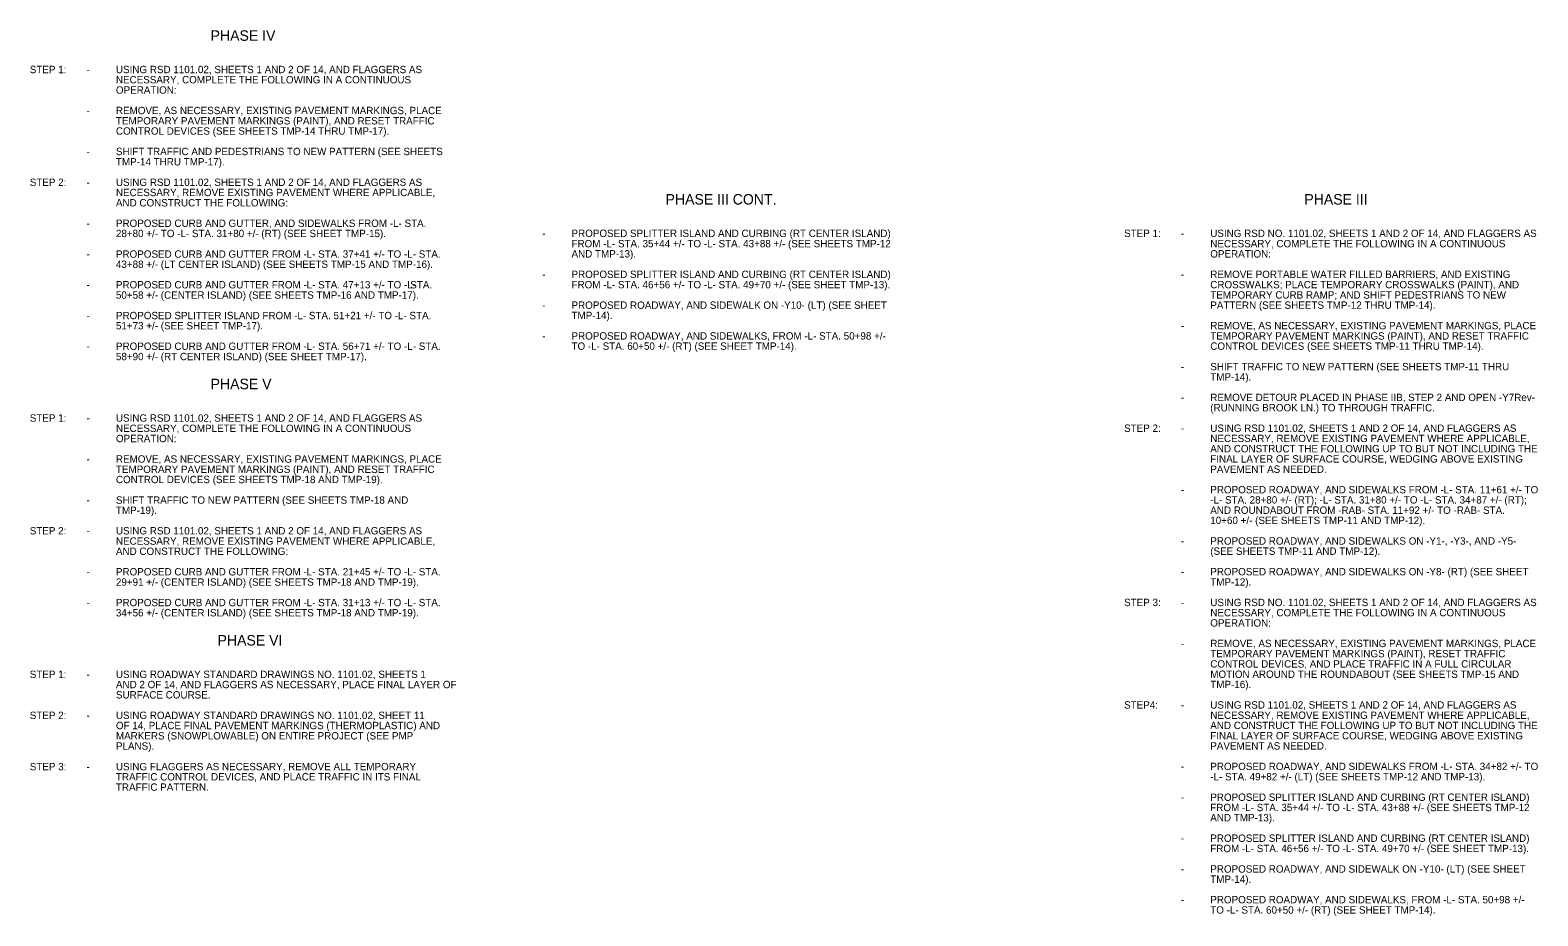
# Model space of a CAD drawing. Extents: x 764226 to 769781, y 650021 to 652521.
# Drawn here: x 768347 to 769781, y 651597 to 652440 of the extents above; entities that cross this region are included whole.
import ezdxf

# ---------------------------------------------------------------- set-up
doc = ezdxf.new("R2010")
doc.units = 0
doc.layers.add('Default', color=7, linetype='Continuous')

msp = doc.modelspace()

# ---------------------------------------------------------------- texts
at = {"layer": 'Default'}
for s, height, p in [('PHASE IV', 10, (768518.4, 652430)), ('STEP 1:', 7, (768346.3, 652399.2)), ('-', 7, (768400.3, 652399.2)), ('USING RSD 1101.02, SHEETS 1 AND 2 OF 14, AND FLAGGERS AS ', 7, (768428.3, 652399.2)), ('OPERATION:', 7, (768428.3, 652379.7)), ('NECESSARY, COMPLETE THE FOLLOWING IN A CONTINUOUS ', 7, (768428.3, 652389.5)), ('-', 7, (768400.3, 652360.2)), ('TEMPORARY PAVEMENT MARKINGS (PAINT), AND RESET TRAFFIC ', 7, (768428.3, 652350.4)), ('REMOVE, AS NECESSARY, EXISTING PAVEMENT MARKINGS, PLACE ', 7, (768428.3, 652360.2)), ('CONTROL DEVICES (SEE SHEETS TMP-14 THRU TMP-17).', 7, (768428.3, 652340.7)), ('-', 7, (768400.3, 652321.2)), ('TMP-14 THRU TMP-17).', 7, (768428.3, 652311.4)), ('SHIFT TRAFFIC AND PEDESTRIANS TO NEW PATTERN (SEE SHEETS ', 7, (768428.3, 652321.2)), ('STEP 2:', 7, (768346.3, 652291.9)), ('-', 7, (768400.3, 652291.9)), ('USING RSD 1101.02, SHEETS 1 AND 2 OF 14, AND FLAGGERS AS ', 7, (768428.3, 652291.9)), ('NECESSARY, REMOVE EXISTING PAVEMENT WHERE APPLICABLE, ', 7, (768428.3, 652282.2)), ('AND CONSTRUCT THE FOLLOWING:', 7, (768428.3, 652272.4)), ('PHASE III CONT.', 10, (768951.3, 652274.2)), ('PHASE III', 10, (769559.1, 652274.2)), ('PROPOSED CURB AND GUTTER, AND SIDEWALKS FROM -L- STA. ', 7, (768428.3, 652252.9)), ('-', 7, (768400.3, 652252.9)), ('28+80 +/- TO -L- STA. 31+80 +/- (RT) (SEE SHEET TMP-15). ', 7, (768428.3, 652243.2)), ('-', 7, (768833.8, 652243.3)), ('PROPOSED SPLITTER ISLAND AND CURBING (RT CENTER ISLAND) ', 7, (768861.8, 652243.3)), ('STEP 1:', 7, (769387.6, 652243.3)), ('-', 7, (769441.6, 652243.3)), ('USING RSD NO. 1101.02, SHEETS 1 AND 2 OF 14, AND FLAGGERS AS ', 7, (769469.6, 652243.3)), ('PROPOSED CURB AND GUTTER FROM -L- STA. 37+41 +/- TO -L- STA. ', 7, (768428.3, 652223.6)), ('AND TMP-13).', 7, (768861.8, 652223.8)), ('FROM -L- STA. 35+44 +/- TO -L- STA. 43+88 +/- (SEE SHEETS TMP-12 ', 7, (768861.8, 652233.5)), ('OPERATION:', 7, (769469.6, 652223.8)), ('NECESSARY, COMPLETE THE FOLLOWING IN A CONTINUOUS ', 7, (769469.6, 652233.5)), ('-', 7, (768400.3, 652223.6)), ('43+88 +/- (LT CENTER ISLAND) (SEE SHEETS TMP-15 AND TMP-16).', 7, (768428.3, 652213.9)), ('PROPOSED CURB AND GUTTER FROM -L- STA. 47+13 +/- TO -L-', 7, (768428.3, 652194.4)), ('STA. ', 7, (768708.4, 652194.4)), ('-', 7, (768833.8, 652204.3)), ('PROPOSED SPLITTER ISLAND AND CURBING (RT CENTER ISLAND) ', 7, (768861.8, 652204.3)), ('FROM -L- STA. 46+56 +/- TO -L- STA. 49+70 +/- (SEE SHEET TMP-13).', 7, (768861.8, 652194.5)), ('-', 7, (769441.6, 652204.3)), ('CROSSWALKS; PLACE TEMPORARY CROSSWALKS (PAINT), AND ', 7, (769469.6, 652194.5)), ('REMOVE PORTABLE WATER FILLED BARRIERS, AND EXISTING ', 7, (769469.6, 652204.3)), ('-', 7, (768400.3, 652194.4)), ('50+58 +/- (CENTER ISLAND) (SEE SHEETS TMP-16 AND TMP-17).', 7, (768428.3, 652184.6)), ('TEMPORARY CURB RAMP; AND SHIFT PEDESTRIANS TO NEW ', 7, (769469.6, 652184.7)), ('PROPOSED SPLITTER ISLAND FROM -L- STA. 51+21 +/- TO -L- STA. ', 7, (768428.3, 652165.1)), ('-', 7, (768833.8, 652175)), ('TMP-14).', 7, (768861.8, 652165.2)), ('PROPOSED ROADWAY, AND SIDEWALK ON -Y10- (LT) (SEE SHEET ', 7, (768861.8, 652175)), ('PATTERN (SEE SHEETS TMP-12 THRU TMP-14).', 7, (769469.6, 652175)), ('-', 7, (768400.3, 652165.1)), ('51+73 +/- (SEE SHEET TMP-17).', 7, (768428.3, 652155.4)), ('-', 7, (769441.6, 652155.5)), ('REMOVE, AS NECESSARY, EXISTING PAVEMENT MARKINGS, PLACE ', 7, (769469.6, 652155.5)), ('PROPOSED CURB AND GUTTER FROM -L- STA. 56+71 +/- TO -L- STA. ', 7, (768428.3, 652135.9)), ('-', 7, (768833.8, 652145.7)), ('TO -L- STA. 60+50 +/- (RT) (SEE SHEET TMP-14).', 7, (768861.8, 652136)), ('PROPOSED ROADWAY, AND SIDEWALKS, FROM -L- STA. 50+98 +/- ', 7, (768861.8, 652145.7)), ('TEMPORARY PAVEMENT MARKINGS (PAINT), AND RESET TRAFFIC ', 7, (769469.6, 652145.7)), ('CONTROL DEVICES (SEE SHEETS TMP-11 THRU TMP-14).', 7, (769469.6, 652136)), ('-', 7, (768400.3, 652135.9)), ('58+90 +/- (RT CENTER ISLAND) (SEE SHEET TMP-17).', 7, (768428.3, 652126.1)), ('-', 7, (769441.6, 652116.5)), ('TMP-14).', 7, (769469.6, 652106.7)), ('SHIFT TRAFFIC TO NEW PATTERN (SEE SHEETS TMP-11 THRU ', 7, (769469.6, 652116.5)), ('PHASE V', 10, (768518.4, 652098.5)), ('-', 7, (769441.6, 652087.2)), ('REMOVE DETOUR PLACED IN PHASE IIB, STEP 2 AND OPEN -Y7Rev- ', 7, (769469.6, 652087.2)), ('STEP 1:', 7, (768346.3, 652067.6)), ('-', 7, (768400.3, 652067.6)), ('USING RSD 1101.02, SHEETS 1 AND 2 OF 14, AND FLAGGERS AS ', 7, (768428.3, 652067.6)), ('(RUNNING BROOK LN.) TO THROUGH TRAFFIC.', 7, (769469.6, 652077.4)), ('NECESSARY, COMPLETE THE FOLLOWING IN A CONTINUOUS ', 7, (768428.3, 652057.8)), ('STEP 2:', 7, (769387.6, 652057.9)), ('-', 7, (769441.6, 652057.9)), ('USING RSD 1101.02, SHEETS 1 AND 2 OF 14, AND FLAGGERS AS ', 7, (769469.6, 652057.9)), ('OPERATION:', 7, (768428.3, 652048.1)), ('AND CONSTRUCT THE FOLLOWING UP TO BUT NOT INCLUDING THE ', 7, (769469.6, 652038.4)), ('NECESSARY, REMOVE EXISTING PAVEMENT WHERE APPLICABLE, ', 7, (769469.6, 652048.2)), ('-', 7, (768400.3, 652028.6)), ('REMOVE, AS NECESSARY, EXISTING PAVEMENT MARKINGS, PLACE ', 7, (768428.3, 652028.6)), ('FINAL LAYER OF SURFACE COURSE, WEDGING ABOVE EXISTING ', 7, (769469.6, 652028.7)), ('TEMPORARY PAVEMENT MARKINGS (PAINT), AND RESET TRAFFIC ', 7, (768428.3, 652018.8)), ('CONTROL DEVICES (SEE SHEETS TMP-18 AND TMP-19).', 7, (768428.3, 652009.1)), ('PAVEMENT AS NEEDED.', 7, (769469.6, 652018.9)), ('-', 7, (769441.6, 651999.4)), ('PROPOSED ROADWAY, AND SIDEWALKS FROM -L- STA. 11+61 +/- TO ', 7, (769469.6, 651999.4)), ('-', 7, (768400.3, 651989.5)), ('TMP-19).', 7, (768428.3, 651979.8)), ('SHIFT TRAFFIC TO NEW PATTERN (SEE SHEETS TMP-18 AND ', 7, (768428.3, 651989.5)), ('AND ROUNDABOUT FROM -RAB- STA. 11+92 +/- TO -RAB- STA. ', 7, (769469.6, 651979.9)), ('-L- STA. 28+80 +/- (RT); -L- STA. 31+80 +/- TO -L- STA. 34+87 +/- (RT); ', 7, (769469.6, 651989.7)), ('10+60 +/- (SEE SHEETS TMP-11 AND TMP-12). ', 7, (769469.6, 651970.2)), ('STEP 2:', 7, (768346.3, 651960.3)), ('-', 7, (768400.3, 651960.3)), ('USING RSD 1101.02, SHEETS 1 AND 2 OF 14, AND FLAGGERS AS ', 7, (768428.3, 651960.3)), ('NECESSARY, REMOVE EXISTING PAVEMENT WHERE APPLICABLE, ', 7, (768428.3, 651950.5)), ('PROPOSED ROADWAY, AND SIDEWALKS ON -Y1-, -Y3-, AND -Y5- ', 7, (769469.6, 651950.6)), ('AND CONSTRUCT THE FOLLOWING:', 7, (768428.3, 651940.8)), ('-', 7, (769441.6, 651950.6)), ('(SEE SHEETS TMP-11 AND TMP-12).', 7, (769469.6, 651940.9)), ('PROPOSED CURB AND GUTTER FROM -L- STA. 21+45 +/- TO -L- STA. ', 7, (768428.3, 651921.3)), ('PROPOSED ROADWAY, AND SIDEWALKS ON -Y8- (RT) (SEE SHEET ', 7, (769469.6, 651921.4)), ('-', 7, (768400.3, 651921.3)), ('29+91 +/- (CENTER ISLAND) (SEE SHEETS TMP-18 AND TMP-19).', 7, (768428.3, 651911.5)), ('-', 7, (769441.6, 651921.4)), ('TMP-12).', 7, (769469.6, 651911.6)), ('PROPOSED CURB AND GUTTER FROM -L- STA. 31+13 +/- TO -L- STA. ', 7, (768428.3, 651892)), ('STEP 3:', 7, (769387.6, 651892.1)), ('USING RSD NO. 1101.02, SHEETS 1 AND 2 OF 14, AND FLAGGERS AS ', 7, (769469.6, 651892.1)), ('-', 7, (768400.3, 651892)), ('34+56 +/- (CENTER ISLAND) (SEE SHEETS TMP-18 AND TMP-19).', 7, (768428.3, 651882.3)), ('-', 7, (769441.6, 651892.1)), ('NECESSARY, COMPLETE THE FOLLOWING IN A CONTINUOUS ', 7, (769469.6, 651882.4)), ('OPERATION: ', 7, (769469.6, 651872.6)), ('PHASE VI', 10, (768525, 651854.6)), ('-', 7, (769441.6, 651853.1)), ('REMOVE, AS NECESSARY, EXISTING PAVEMENT MARKINGS, PLACE ', 7, (769469.6, 651853.1)), ('TEMPORARY PAVEMENT MARKINGS (PAINT), RESET TRAFFIC ', 7, (769469.6, 651843.4)), ('STEP 1:', 7, (768346.3, 651823.7)), ('-', 7, (768400.3, 651823.7)), ('USING ROADWAY STANDARD DRAWINGS NO. 1101.02, SHEETS 1 ', 7, (768428.3, 651823.7)), ('CONTROL DEVICES, AND PLACE TRAFFIC IN A FULL CIRCULAR ', 7, (769469.6, 651833.6)), ('MOTION AROUND THE ROUNDABOUT (SEE SHEETS TMP-15 AND ', 7, (769469.6, 651823.8)), ('AND 2 OF 14, AND FLAGGERS AS NECESSARY, PLACE FINAL LAYER OF ', 7, (768428.3, 651814)), ('TMP-16).', 7, (769469.6, 651814.1)), ('SURFACE COURSE.', 7, (768428.3, 651804.2)), ('STEP4:', 7, (769387.6, 651794.6)), ('USING RSD 1101.02, SHEETS 1 AND 2 OF 14, AND FLAGGERS AS ', 7, (769469.6, 651794.6)), ('STEP 2:', 7, (768346.3, 651784.7)), ('-', 7, (768400.3, 651784.7)), ('USING ROADWAY STANDARD DRAWINGS NO. 1101.02, SHEET 11 ', 7, (768428.3, 651784.7)), ('-', 7, (769441.6, 651794.6)), ('NECESSARY, REMOVE EXISTING PAVEMENT WHERE APPLICABLE, ', 7, (769469.6, 651784.8)), ('OF 14, PLACE FINAL PAVEMENT MARKINGS (THERMOPLASTIC) AND ', 7, (768428.3, 651775)), ('MARKERS (SNOWPLOWABLE) ON ENTIRE PROJECT (SEE PMP ', 7, (768428.3, 651765.2)), ('AND CONSTRUCT THE FOLLOWING UP TO BUT NOT INCLUDING THE ', 7, (769469.6, 651775.1)), ('FINAL LAYER OF SURFACE COURSE, WEDGING ABOVE EXISTING ', 7, (769469.6, 651765.3)), ('PLANS).', 7, (768428.3, 651755.5)), ('PAVEMENT AS NEEDED.', 7, (769469.6, 651755.6)), ('STEP 3:', 7, (768346.3, 651735.9)), ('USING FLAGGERS AS NECESSARY, REMOVE ALL TEMPORARY ', 7, (768428.3, 651735.9)), ('PROPOSED ROADWAY, AND SIDEWALKS FROM -L- STA. 34+82 +/- TO ', 7, (769469.6, 651736.1)), ('-', 7, (768400.3, 651735.9)), ('TRAFFIC CONTROL DEVICES, AND PLACE TRAFFIC IN ITS FINAL ', 7, (768428.3, 651726.2)), ('-', 7, (769441.6, 651736.1)), ('-L- STA. 49+82 +/- (LT) (SEE SHEETS TMP-12 AND TMP-13).', 7, (769469.6, 651726.3)), ('TRAFFIC PATTERN.', 7, (768428.3, 651716.4)), ('PROPOSED SPLITTER ISLAND AND CURBING (RT CENTER ISLAND) ', 7, (769469.6, 651706.8)), ('-', 7, (769441.6, 651706.8)), ('FROM -L- STA. 35+44 +/- TO -L- STA. 43+88 +/- (SEE SHEETS TMP-12 ', 7, (769469.6, 651697)), ('AND TMP-13).', 7, (769469.6, 651687.3)), ('-', 7, (769441.6, 651667.8)), ('PROPOSED SPLITTER ISLAND AND CURBING (RT CENTER ISLAND) ', 7, (769469.6, 651667.8)), ('FROM -L- STA. 46+56 +/- TO -L- STA. 49+70 +/- (SEE SHEET TMP-13).', 7, (769469.6, 651658)), ('-', 7, (769441.6, 651638.5)), ('PROPOSED ROADWAY, AND SIDEWALK ON -Y10- (LT) (SEE SHEET ', 7, (769469.6, 651638.5)), ('TMP-14).', 7, (769469.6, 651628.8)), ('-', 7, (769441.6, 651609.3)), ('PROPOSED ROADWAY, AND SIDEWALKS, FROM -L- STA. 50+98 +/- ', 7, (769469.6, 651609.3)), ('TO -L- STA. 60+50 +/- (RT) (SEE SHEET TMP-14).', 7, (769469.6, 651599.5))]:
    msp.add_text(s, height=height, rotation=359.9999, dxfattribs=at).set_placement(p)

doc.saveas('drawing.dxf')
